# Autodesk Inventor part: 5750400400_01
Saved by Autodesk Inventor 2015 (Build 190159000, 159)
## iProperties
Created: 2020-07
Part Number: 5750400400_01
Checked By: TraceParts S.A.
Material: Generic
Catalog Web Link: www.traceparts.com
Document SubType Name: Modeling
Designer: TraceParts
Density: 1 g/cm^3
Appearance: Default
Company: TraceParts S.A.
Author: TraceParts
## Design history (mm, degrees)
feature "5750400400_01.ipt"
body "Solid1"
